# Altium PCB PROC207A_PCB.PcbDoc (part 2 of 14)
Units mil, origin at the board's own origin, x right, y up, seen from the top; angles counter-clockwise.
Board outline 4094.49 x 3724.79 mil, 8 copper layers (Top Layer, L2_GND1, L3_SIG1, L4_PWR1, L5_PWR2, L6_SIG2, L7_GND2, Bottom Layer), stack 58.1 mil thick; 584 components, 399 nets, 8440 pads, 5258 vias.
Unrouted connection lines stored in the file: 9.
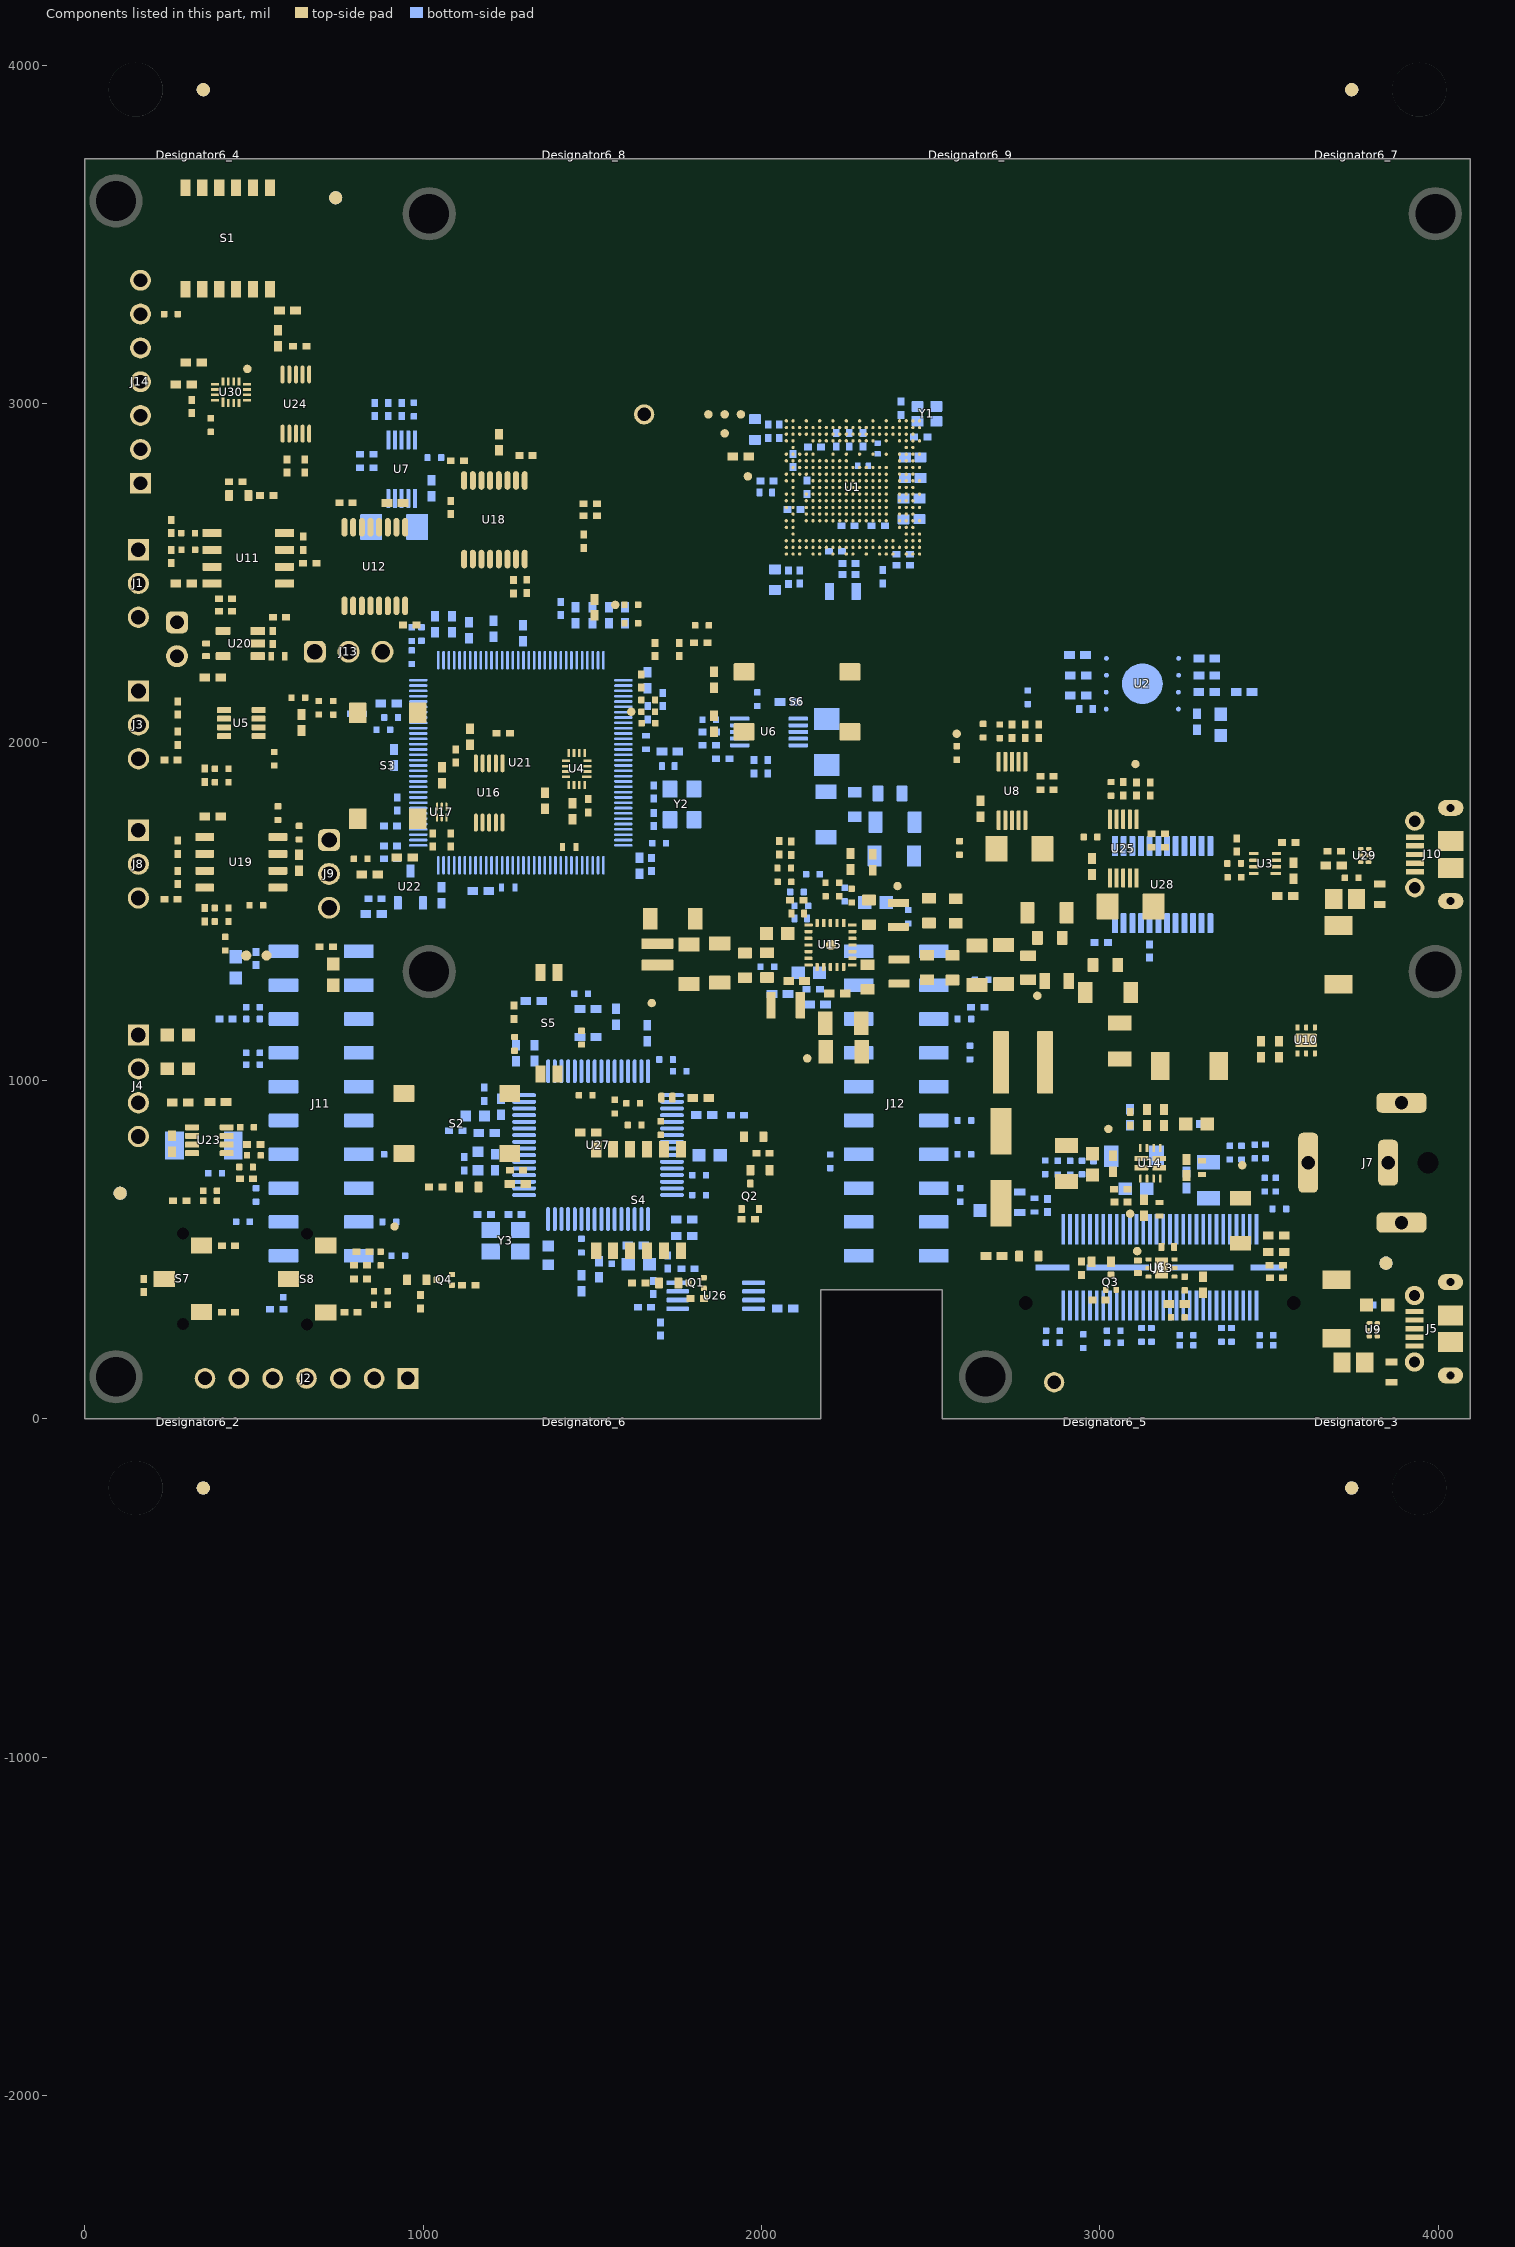
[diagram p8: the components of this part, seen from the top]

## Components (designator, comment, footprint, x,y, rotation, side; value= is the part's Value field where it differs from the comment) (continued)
R185 "CRCW04022K20JNED" 0402L 1679.65,388.39 r270 bottom value=2.2k
R186 "CRCW040233R2FKED" 0402 1273.96,1081.16 r90 bottom value=33.2
R187 "CRCW040233R2FKED" 0402 1326.93,1234.64 r180 bottom value=33.2
R188 "ERJ-2GE0R00X" FP-ERJ-2GE0R00X_0402-MFG 966.13,2251.35 r270 bottom value=0
R189 "ERJ-2GE0R00X" FP-ERJ-2GE0R00X_0402-MFG 1466.82,1256.68 r0 bottom value=0
R190 "ERJ-2GE0R00X" FP-ERJ-2GE0R00X_0402-MFG 905.18,2073.18 r0 bottom value=0
R191 "ERJ-2RKF1001X" 0402 1596.96,2375.29 r90 bottom value=1.00k
R192 "WSL1206R0400FEB" FP-WSL1206R0400FEB_1206-MFG 2193,2000.99 r90 bottom value=40m
R193 "WSL1206R0200FEB" FP-WSL1206R0200FEB_1206-MFG 2762.36,1684.93 r180 top value=20m
R194 "ERJ-2RKF1001X" 0402 1549.54,2375.29 r90 bottom value=1.00k
R195 "ERJ-2RKF1001X" 0402 1500.19,2375.63 r90 bottom value=1.00k
R196 "ERJ-2RKF1001X" 0402 1449.62,2375.63 r90 bottom value=1.00k
R197 "ERJ-2GE0R00X" FP-ERJ-2GE0R00X_0402-MFG 1467.94,1126.6 r270 top value=0
R198 "ERJ-2GE0R00X" FP-ERJ-2GE0R00X_0402-MFG 496.87,1047 r0 bottom value=0
R199 "ERJ-2GE0R00X" FP-ERJ-2GE0R00X_0402-MFG 1269.99,1108.46 r270 top value=0
R200 "WSL1206R0400FEB" FP-WSL1206R0400FEB_1206-MFG 914.18,2636.19 r0 bottom value=40m
R201 "ERJ-2GE0R00X" FP-ERJ-2GE0R00X_0402-MFG 2599.66,882 r0 bottom value=0
R202 "CRCW040249R9FKED" 0402L 1708.21,2126.64 r90 bottom value=49.9
R203 "CRCW040210K0FKED" 0402L 174.2,393.97 r90 top value=10.0k
R204 "CRCW04027K87FKED" 0402L 424.12,512.08 r0 top value=7.87k
R205 "CRCW040282K5FKED" 0402L 424.12,315.23 r180 top value=82.5k
R206 "CRCW040210K0FKED" 0402L 814.41,453.57 r180 top value=10.0k
R207 "CRCW04027K87FKED" 0402L 821.81,494.32 r0 top value=7.87k
R208 "CRCW040282K5FKED" 0402L 786.57,314.86 r180 top value=82.5k
R209 "CRCW040233R2FKED" 0402 1486.9,1211.99 r0 bottom value=33.2
R210 "ERJ-2GE0R00X" FP-ERJ-2GE0R00X_0402-MFG 384.82,726 r0 bottom value=0
R211 "ERJ-2GE0R00X" FP-ERJ-2GE0R00X_0402-MFG 904.66,782 r0 bottom value=0
R212 "ERJ-2GE0R00X" FP-ERJ-2GE0R00X_0402-MFG 2202.92,761.33 r90 bottom value=0
R213 "CRCW0402220RJNED" 0402 945.08,1658.85 r180 top value=220
R214 "ERJ-2GE0R00X" FP-ERJ-2GE0R00X_0402-MFG 815,1655.53 r0 top value=0
R215 "CRCW0402100KFKED" 0402 842.27,1609.44 r0 top value=100k
R216 "ERJ-2GE0R00X" FP-ERJ-2GE0R00X_0402-MFG 1717.94,1062.08 r0 bottom value=0
R217 "ERJ-2GE0R00X" FP-ERJ-2GE0R00X_0402-MFG 1758.3,1027.08 r180 bottom value=0
R218 "CRCW040210K0FKED" 0402L 1096.37,851.44 r0 bottom value=10.0k
R219 "ERJ-2GE0R00X" FP-ERJ-2GE0R00X_0402-MFG 3123.48,248.24 r270 bottom value=0
R220 "ERJ-2GE0R00X" FP-ERJ-2GE0R00X_0402-MFG 3152.67,248.24 r270 bottom value=0
R221 "ERJ-2GE0R00X" FP-ERJ-2GE0R00X_0402-MFG 2599.66,782 r0 bottom value=0
R222 "ERJ-2GE0R00X" FP-ERJ-2GE0R00X_0402-MFG 505.82,661.82 r90 bottom value=0
R223 "ERJ-2GE0R00X" FP-ERJ-2GE0R00X_0402-MFG 2587.42,661.82 r270 bottom value=0
R224 "ERJ-2GE0R00X" FP-ERJ-2GE0R00X_0402-MFG 467,582.78 r0 bottom value=0
R225 "ERJ-2GE0R00X" FP-ERJ-2GE0R00X_0402-MFG 3256.43,247.17 r180 bottom value=0
R226 "ERJ-2GE0R00X" FP-ERJ-2GE0R00X_0402-MFG 3256.43,217.48 r180 bottom value=0
R227 "ERJ-2GE0R00X" FP-ERJ-2GE0R00X_0402-MFG 3359.7,248.24 r270 bottom value=0
R228 "ERJ-2GE0R00X" FP-ERJ-2GE0R00X_0402-MFG 3389.38,248.24 r270 bottom value=0
R229 "ERJ-2GE0R00X" FP-ERJ-2GE0R00X_0402-MFG 3492.64,217.48 r0 bottom value=0
R230 "ERJ-2GE0R00X" FP-ERJ-2GE0R00X_0402-MFG 3492.64,247.17 r0 bottom value=0
R231 "CRCW040210K0FKED" 0402L 1663.56,2087.29 r90 bottom value=10.0k
R232 "ERJ-2GE0R00X" FP-ERJ-2GE0R00X_0402-MFG 899.66,582 r0 bottom value=0
R233 "ERJ-2RKF1001X" 0402 1054.11,1547.47 r270 bottom value=1.00k
R234 "CRCW04024K87FKED" 0402L 1406.98,2395.63 r270 bottom value=4.87k
R235 "ERJ-2GE0R00X" FP-ERJ-2GE0R00X_0402-MFG 369.87,674.49 r0 top value=0
R236 "CRCW0402330KFKED" 0402L 903.11,1752.47 r180 bottom value=330k
R237 "ERJ-2RKF1001X" 0402 1328.96,1081.22 r270 bottom value=1.00k
R238 "ERJ-2GE0R00X" FP-ERJ-2GE0R00X_0402-MFG 586.27,379.55 r90 bottom value=0
R239 "CRCW0402330KFKED" 0402L 903.11,1655.47 r0 bottom value=330k
R240 "ERJ-2GE0R00X" FP-ERJ-2GE0R00X_0402-MFG 926.22,482 r0 bottom value=0
R241 "ERJ-2GE0R00X" FP-ERJ-2GE0R00X_0402-MFG 3251.04,399.98 r90 top value=0
R242 "ERJ-2GE0R00X" FP-ERJ-2GE0R00X_0402-MFG 1467.83,511.73 r270 bottom value=0
R243 "ERJ-2GE0R00X" FP-ERJ-2GE0R00X_0402-MFG 1815.53,720.47 r0 bottom value=0
R244 "ERJ-2GE0R00X" FP-ERJ-2GE0R00X_0402-MFG 874.72,337.37 r0 top value=0
R245 "ERJ-2GE0R00X" FP-ERJ-2GE0R00X_0402-MFG 2067.24,1628.18 r0 top value=0
R246 "CRCW0402100KFKED" 0402L 2419.43,2523.33 r180 bottom value=100k
R247 "CRCW040210K0FKED" 0402L 1685.11,2274.26 r270 top value=10.0k
R248 "CRCW040233R2FKED" 0402 1519.16,441.79 r270 bottom locked value=33.2
R249 "CRCW040233R2FKED" 0402 1468.31,401.1 r270 bottom value=33.2
R250 "CRCW040210K0FKED" 0402L 1494.18,2669.49 r180 top value=10.0k
R251 "CRCW040233R2FKED" 0402 1830.79,897.64 r0 bottom value=33.2
R252 "ERJ-2GEJ511X" 0402L 1929.07,897.64 r0 bottom value=510
R253 "CRCW040210K0FKED" 0402L 635.36,3171.01 r180 top value=10.0k
R254 "ERJ-2GE0R00X" FP-ERJ-2GE0R00X_0402-MFG 414.56,1404.55 r90 top value=0
R255 "CRCW0402100KFKED" 0402L 1474.36,2594.42 r90 top value=100k
R256 "CRCW0402100KFKED" 0402L 1081.26,2694.18 r270 top value=100k
R257 "ERJ-2GE0R00X" FP-ERJ-2GE0R00X_0402-MFG 2576.93,1968.47 r90 top value=0
R258 "ERJ-2GEJ511X" 0402L 2946.06,444.73 r270 top value=510
R259 "ERJ-2GE0R00X" FP-ERJ-2GE0R00X_0402-MFG 3744.42,1599.14 r0 top value=0
R260 "CRCW040230K0FKED" 0402L 3692.79,1677.42 r0 top value=30.0k
R261 "CRCW040210K0FKED" 0402L 1757.13,2274.4 r90 top value=10.0k
R262 "CRCW0402220RJNED" 0402 1859.79,2054.47 r90 top value=220
R263 "ERJ-2GEJ511X" 0402L 2997.55,351.35 r180 top value=510
R264 "ERJ-2GE0R00X" FP-ERJ-2GE0R00X_0402-MFG 1615.08,2351.95 r0 top value=0
R265 "CRCW0402100KFKED" 0402 1859.79,2184.39 r270 top value=100k
R266 "ERJ-2GE0R00X" FP-ERJ-2GE0R00X_0402-MFG 734.45,2101.84 r270 top value=0
R267 "ERJ-2GE0R00X" FP-ERJ-2GE0R00X_0402-MFG 1665.13,2090.04 r180 top value=0
R268 "ERJ-2GE0R00X" FP-ERJ-2GE0R00X_0402-MFG 1665.13,2125.04 r180 top value=0
R269 "ERJ-2GE0R00X" FP-ERJ-2GE0R00X_0402-MFG 1615.08,2406.15 r0 top value=0
R270 "ERJ-2GE0R00X" FP-ERJ-2GE0R00X_0402-MFG 1665.95,2056.5 r180 top value=0
R271 "CRCW040210K0FKED" 0402L 315.66,2992.42 r90 top value=10.0k
R272 "RC0402FR-074K7L" 0402 321.95,3122.76 r0 top value=4.70k
R273 "ERJ-2GE0R00X" FP-ERJ-2GE0R00X_0402-MFG 404.36,1921.85 r180 top value=0
R274 "CRCW0402100KFKED" 0402L 597.17,2816.9 r270 top value=100k
R275 "CRCW0402100KFKED" 0402L 650.21,2816.9 r270 top value=100k
R276 "CRCW040210K0FKED" 0402L 1819.98,2294.33 r0 top value=10.0k
R277 "ERJ-2RKF1001X" 0402 598.62,3276 r0 top value=1.00k
R278 "ERJ-2GE0R00X" FP-ERJ-2GE0R00X_0402-MFG 2209.63,1544.82 r180 top value=0
R279 "ERJ-2GE0R00X" FP-ERJ-2GE0R00X_0402-MFG 2104.75,1557.54 r180 bottom value=0
R280 "ERJ-2GE0R00X" FP-ERJ-2GE0R00X_0402-MFG 2017.44,1336.5 r180 bottom value=0
R281 "ERJ-2GE0R00X" FP-ERJ-2GE0R00X_0402-MFG 2246.12,1549.78 r90 bottom value=0
R282 "ERJ-2GE0R00X" FP-ERJ-2GE0R00X_0402-MFG 2650.92,1297.66 r0 bottom value=0
R283 "CRCW040210K0FKED" 0402L 3558.84,1703.48 r180 top value=10.0k
R284 "ERJ-2GE0R00X" FP-ERJ-2GE0R00X_0402-MFG 2787,2133 r90 bottom value=0
R285 "ERJ-2GE0R00X" FP-ERJ-2GE0R00X_0402-MFG 371.87,2937.61 r90 top value=0
R286 "ERJ-2GE0R00X" FP-ERJ-2GE0R00X_0402-MFG 254.35,3265.75 r0 top value=0
R287 "ERJ-2GEJ511X" 0402L 1036.61,685.39 r180 top value=510
R288 "CRCW040210K0FKED" 0402L 2152.76,1269.69 r0 bottom value=10.0k
R289 "CRCW040219K1FKED" 0402 2054.68,1256.14 r0 bottom value=19.1k
R290 "ERJ-2GE0R00X" FP-ERJ-2GE0R00X_0402-MFG 882,2037 r0 bottom value=0
S1 "218-6LPST" SW_218-6LPST 421.89,3489.18 r270 top
S2 "PTS645SM43SMTR92 LFS" SW_PTS645SM43SMT 1099.52,872.95 r0 top
S3 "PTS645SM43SMTR92 LFS" SW_PTS645SM43SMT 895.12,1930.34 r270 top
S4 "218-6LPST" SW_218-6LPST 1636.51,646.87 r90 top
S5 "218-2LPST" SW_218-2LP 1371.54,1169.13 r270 top
S6 "PTS645SM43SMTR92 LFS" SW_PTS645SM43SMT 2104.9,2119.43 r180 top
S7 "CL-SB-12A-01T" SW_CL-SB-12A-01 289.32,413.65 r180 top
S8 "CL-SB-12A-01T" SW_CL-SB-12A-01 656.77,413.28 r180 top
TP1 "TESTPOINT" TP_25MIL-SMT 915.24,568.56 r270 top
TP2 "TESTPOINT" TP_25MIL-SMT 1843,2969.15 r90 top
TP3 "TESTPOINT" TP_25MIL-SMT 2576.93,2025.16 r90 top
TP4 "TESTPOINT" TP_25MIL-SMT 480.15,3103.58 r180 top
TP5 "TESTPOINT" TP_25MIL-SMT 1959.66,2785.99 r90 top
TP6 "TESTPOINT" TP_25MIL-SMT 1891.06,2913 r90 top
TP7 "TESTPOINT" TP_25MIL-SMT 3025.55,856.91 r90 top
TP8 "TESTPOINT" TP_25MIL-SMT 1614.95,2090.04 r90 top
TP9 "TESTPOINT" TP_25MIL-SMT 1567.54,2405.99 r90 top
TP11 "TESTPOINT" TP_25MIL-SMT 1939.12,2969.15 r90 top
TP12 "TESTPOINT" TP_25MIL-SMT 1891.06,2969.15 r90 top
TP13 "TESTPOINT" TP_25MIL-SMT 3089.63,606.28 r90 top
TP14 "TESTPOINT" TP_25MIL-SMT 3421.13,749.44 r90 top
TP15 "TESTPOINT" TP_25MIL-SMT 2135.09,1065.51 r90 top
TP16 "TESTPOINT" TP_25MIL-SMT 1675.43,1229.15 r270 top
TP17 "TESTPOINT" TP_25MIL-SMT 3105.44,1935.65 r90 top
TP18 "TESTPOINT" TP_25MIL-SMT 2402,1575 r90 top
TP19 "TESTPOINT" TP_25MIL-SMT 2815.34,1250.55 r90 top
TP20 "TESTPOINT" TP_25MIL-SMT 3110.45,495.88 r90 top
TP21 "TESTPOINT" TP_VIA_060RND040 2865,108 r90 top
TP22 "TESTPOINT" TP_VIA_060RND040 1653,2969.15 r90 top
U1 "XA6888DBSAPD" 0-MFG 2270.32,2753.25 r270 top
U2 "MX25V1635FZNQ03" FP-MX25V1635FZNQ03_WSON8-MFG 3126,2173 r0 bottom
U3 "TMP451AQDQFRQ1" DQF0008A 3488.89,1641.5 r180 top
U4 "TS3A5018RSVR" RSV0016A 1453.74,1921.26 r180 top
U5 "TCAN1044AVDDFRQ1" DDF0008A-MFG 462.45,2056.85 r180 top
U6 "INA228AIDGST" DGS0010A-MFG 2022.05,2030.52 r0 bottom
U7 "INA228AIDGST" DGS0010A-MFG 936.06,2807.15 r270 bottom
U8 "INA228AIDGST" DGS0010A-MFG 2740.47,1855.88 r270 top
U9 "TPD4E004DRYR" DRY0006A 3808.54,263.22 r0 top
U10 "TVS1800DRVR" DRV0006A 3610.07,1118.68 r270 top
U11 "CAT24C08WI-GT3" SOIC-8 482.9,2543.79 r180 top
U12 "TS3A44159PWR" PW0016A_N 856.89,2519.38 r90 top
U13 "TLV75533PDRVR" DRV0006A 3182.65,445.74 r0 top
U14 "TPS2121RUXR" RUX0012A 3149.19,755.07 r180 top
U15 "TPS65036501RAYRQ1" RAY0024B-MFG 2203.66,1400.77 r0 top locked
U16 "TS3A24157DGSR" DGS0010A_N 1194.96,1850.25 r90 top
U17 "SN74LVC1G11DSFR" DSF0006A 1054.8,1793.8 r90 top
U18 "TS3A44159PWR" PW0016A_N 1210.47,2657.7 r90 top
U19 "TCAN3403DRQ1" D0008B-MFG 462.28,1645.14 r180 top
U20 "TPS78417QDBVRQ1" DBV0005A-MFG 459.49,2291.81 r180 top
U21 "TM4C1294NCPDTT3" PDT0128A 1288.51,1939.32 r0 bottom locked
U22 "LM4040C25QDBZR" DBZ0003A_N 962.11,1572.47 r90 bottom
U23 "TLIN1039DDFRQ1" DDF0008A-MFG 367.95,823.53 r180 top
U24 "TS3A24157DGSR" DGS0010A_N 623.69,2999.86 r90 top
U25 "INA228AIDGST" DGS0010A-MFG 3069.32,1685.64 r270 top
U26 "93LC46B-I/ST" TSSOP-8 1864.18,363.88 r0 bottom
U27 "FT4232HL" LQFP64_N 1516.85,809.06 r0 bottom locked
U28 "TS3A27518EPWR" PW0024A-MFG 3185.8,1579.22 r270 bottom
U29 "TPD4E004DRYR" DRY0006A 3783.23,1665.25 r180 top
U30 "TS3A5018RSVR" RSV0016A 431.86,3034.84 r90 top
Y1 "FW4000044Q" FP-FW4000044Q_4-SMD-2.0x1.6mm-MFG 2489.06,2970.92 r180 bottom
Y2 "ECS-160-8-33Q-RES-TR" FP-ECS-160-8-33Q-RES-TR_SMT4_3MM2_2MM5-MFG 1764.81,1816.36 r270 bottom
Y3 "NX3225SA-12.000M-STD-CRS-2" NDK_NX3225SA 1243.27,526.6 r90 bottom
ZZ1 "This Assembly Note is for PCB labels only" AssemblyNoteLabel -334.65,4627.95 r0 top
ZZ2 "These assemblies are ESD sensitive, ESD precautions shall be observed." AssemblyNote -337.73,4557.31 r0 top
ZZ3 "These assemblies must be clean and free from flux and all contaminants. Use of no clean flux is not acceptable." AssemblyNote -336.61,4494.1 r0 top
ZZ4 "These assemblies must comply with workmanship standards IPC-A-610 Class 2, unless otherwise specified." AssemblyNote -336.61,4444.88 r0 top
ZZ5 "INDICATION FOR COMPONENTS D* ARE GIVEN AT THEIR CATHODE SIDE." AssemblyNote -336.61,4382.88 r0 top

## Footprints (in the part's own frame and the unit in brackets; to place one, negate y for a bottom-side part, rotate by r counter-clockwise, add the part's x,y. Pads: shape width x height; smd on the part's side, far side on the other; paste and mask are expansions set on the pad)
0-MFG [mm]
  round 0.25 smd paste+0 mask+0.05: A1(-5,5) A2(-4.5,5) A4(-3.5,5) A6(-2.5,5) A8(-1.5,5) A10(-0.5,5) A12(0.5,5) A14(1.5,5) A16(2.5,5) A18(3.5,5) A19(4,5) A20(4.5,5) A21(5,5) AA1(-5,-5) AA2(-4.5,-5) AA3(-4,-5) AA4(-3.5,-5) AA6(-2.5,-5) AA7(-2,-5) AA9(-1,-5) AA10(-0.5,-5) AA12(0.5,-5) AA13(1,-5) AA14(1.5,-5) AA16(2.5,-5) AA17(3,-5) AA19(4,-5) AA20(4.5,-5) AA21(5,-5) B1(-5,4.5) B2(-4.5,4.5) B3(-4,4.5) B4(-3.5,4.5) B5(-3,4.5) B6(-2.5,4.5) B7(-2,4.5) B8(-1.5,4.5) B9(-1,4.5) B10(-0.5,4.5) B11(0,4.5) B12(0.5,4.5) B13(1,4.5) B14(1.5,4.5) B15(2,4.5) B16(2.5,4.5) B17(3,4.5) B18(3.5,4.5) B19(4,4.5) B20(4.5,4.5) B21(5,4.5) C1(-5,4) C2(-4.5,4) C3(-4,4) C4(-3.5,4) C5(-3,4) C6(-2.5,4) C7(-2,4) C8(-1.5,4) C9(-1,4) C10(-0.5,4) C11(0,4) C12(0.5,4) C13(1,4) C14(1.5,4) C15(2,4) C16(2.5,4) C17(3,4) C18(3.5,4) C19(4,4) C20(4.5,4) C21(5,4) D1(-5,3.5) D2(-4.5,3.5) D3(-4,3.5) D4(-3.5,3.5) D6(-2.5,3.5) D7(-2,3.5) D8(-1.5,3.5) D9(-1,3.5) D10(-0.5,3.5) D11(0,3.5) D12(0.5,3.5) D13(1,3.5) D14(1.5,3.5) D15(2,3.5) D16(2.5,3.5) D17(3,3.5) D20(4.5,3.5) E2(-4.5,3) E3(-4,3) E19(4,3) E20(4.5,3) E21(5,3) F1(-5,2.5) F2(-4.5,2.5) F3(-4,2.5) F4(-3.5,2.5) F6(-2.5,2.5) F8(-1.5,2.5) F9(-1,2.5) F10(-0.5,2.5) F11(0,2.5) F12(0.5,2.5) F13(1,2.5) F14(1.5,2.5) F15(2,2.5) F16(2.5,2.5) F19(4,2.5) F20(4.5,2.5) F21(5,2.5) G2(-4.5,2) G3(-4,2) G8(-1.5,2) G9(-1,2) G10(-0.5,2) G11(0,2) G12(0.5,2) G13(1,2) G14(1.5,2) G15(2,2) G16(2.5,2) G20(4.5,2) G21(5,2) H1(-5,1.5) H2(-4.5,1.5) H3(-4,1.5) H4(-3.5,1.5) H6(-2.5,1.5) H8(-1.5,1.5) H9(-1,1.5) H10(-0.5,1.5) H11(0,1.5) H12(0.5,1.5) H13(1,1.5) H14(1.5,1.5) H15(2,1.5) H16(2.5,1.5) H19(4,1.5) H20(4.5,1.5) J2(-4.5,1) J3(-4,1) J4(-3.5,1) J8(-1.5,1) J9(-1,1) J10(-0.5,1) J11(0,1) J12(0.5,1) J13(1,1) J14(1.5,1) J15(2,1) J16(2.5,1) J19(4,1) J20(4.5,1) J21(5,1) K1(-5,0.5) K2(-4.5,0.5) K3(-4,0.5) K4(-3.5,0.5) K6(-2.5,0.5) K8(-1.5,0.5) K9(-1,0.5) K10(-0.5,0.5) K11(0,0.5) K12(0.5,0.5) K13(1,0.5) K14(1.5,0.5) K15(2,0.5) K16(2.5,0.5) K19(4,0.5) K20(4.5,0.5) L2(-4.5,0) L3(-4,0) L4(-3.5,0) L8(-1.5,0) L9(-1,0) L10(-0.5,0) L11(0,0) L12(0.5,0) L13(1,0) L14(1.5,0) L15(2,0) L16(2.5,0) L19(4,0) L20(4.5,0) L21(5,0) M1(-5,-0.5) M2(-4.5,-0.5) M3(-4,-0.5) M4(-3.5,-0.5) M6(-2.5,-0.5) M7(-2,-0.5) M8(-1.5,-0.5) M9(-1,-0.5) M10(-0.5,-0.5) M11(0,-0.5) M12(0.5,-0.5) M13(1,-0.5) M14(1.5,-0.5) M15(2,-0.5) M16(2.5,-0.5) M19(4,-0.5) M20(4.5,-0.5) M21(5,-0.5) N2(-4.5,-1) N3(-4,-1) N4(-3.5,-1) N7(-2,-1) N8(-1.5,-1) N9(-1,-1) N10(-0.5,-1) N11(0,-1) N12(0.5,-1) N13(1,-1) N14(1.5,-1) N15(2,-1) N16(2.5,-1) N19(4,-1) N20(4.5,-1) P1(-5,-1.5) P2(-4.5,-1.5) P3(-4,-1.5) P4(-3.5,-1.5) P6(-2.5,-1.5) P7(-2,-1.5) P8(-1.5,-1.5) P9(-1,-1.5) P10(-0.5,-1.5) P11(0,-1.5) P12(0.5,-1.5) P13(1,-1.5) P14(1.5,-1.5) P15(2,-1.5) P16(2.5,-1.5) P19(4,-1.5) P20(4.5,-1.5) P21(5,-1.5) R2(-4.5,-2) R3(-4,-2) R4(-3.5,-2) R7(-2,-2) R8(-1.5,-2) R9(-1,-2) R10(-0.5,-2) R11(0,-2) R12(0.5,-2) R13(1,-2) R14(1.5,-2) R15(2,-2) R16(2.5,-2) R19(4,-2) R20(4.5,-2) T1(-5,-2.5) T2(-4.5,-2.5) T3(-4,-2.5) T4(-3.5,-2.5) T7(-2,-2.5) T8(-1.5,-2.5) T9(-1,-2.5) T10(-0.5,-2.5) T11(0,-2.5) T12(0.5,-2.5) T13(1,-2.5) T14(1.5,-2.5) T15(2,-2.5) T16(2.5,-2.5) T19(4,-2.5) T20(4.5,-2.5) T21(5,-2.5) U2(-4.5,-3) U3(-4,-3) U4(-3.5,-3) U6(-2.5,-3) U7(-2,-3) U8(-1.5,-3) U9(-1,-3) U10(-0.5,-3) U11(0,-3) U12(0.5,-3) U13(1,-3) U14(1.5,-3) U15(2,-3) U16(2.5,-3) U19(4,-3) U20(4.5,-3) U21(5,-3) V1(-5,-3.5) V2(-4.5,-3.5) V3(-4,-3.5) V6(-2.5,-3.5) V7(-2,-3.5) V8(-1.5,-3.5) V9(-1,-3.5) V12(0.5,-3.5) V13(1,-3.5) V14(1.5,-3.5) V15(2,-3.5) V16(2.5,-3.5) V19(4,-3.5) V20(4.5,-3.5) W2(-4.5,-4) W3(-4,-4) W6(-2.5,-4) W7(-2,-4) W8(-1.5,-4) W9(-1,-4) W19(4,-4) W20(4.5,-4) W21(5,-4) Y1(-5,-4.5) Y2(-4.5,-4.5) Y3(-4,-4.5) Y4(-3.5,-4.5) Y5(-3,-4.5) Y6(-2.5,-4.5) Y7(-2,-4.5) Y8(-1.5,-4.5) Y9(-1,-4.5) Y10(-0.5,-4.5) Y11(0,-4.5) Y12(0.5,-4.5) Y13(1,-4.5) Y14(1.5,-4.5) Y15(2,-4.5) Y16(2.5,-4.5) Y17(3,-4.5) Y18(3.5,-4.5) Y19(4,-4.5) Y20(4.5,-4.5) Y21(5,-4.5)
  silkscreen extent -5.6,-5.6 5.6,5.6, body extent -6.1,-6.1 6.1,6.1, height 0.25
0402 [mm] "0402 from SM-752 data"
  rect 0.8x0.6 smd: 1(-0.6,0) 2(0.6,0)
  silkscreen extent -1.22,-0.52 1.22,0.52, body extent -0.55,-0.3 0.55,0.3, height 0.6
0402_070 [mil] "SMD, 2-Leads, Body 1.2x0.7mm, Height 0.7mm"
  rect 15x24 smd: 1(-20,0) 2(20,0)
  body extent -24,-14 24,14, height 28
0402L [mm] "0402 from SM-752 data"
  rect 0.6x0.5 smd: 1(-0.5,0) 2(0.5,0)
  body extent -0.55,-0.3 0.55,0.3, height 0.6
0603 [mm] "0603 from SM-752 data"
  rect 1x0.95 smd: 1(-0.8,0) 2(0.8,0)
  silkscreen extent -1.52,-0.69 1.52,0.69, body extent -0.87,-0.47 0.87,0.47, height 1
0603L [mm] "0603 from SM-752 data"
  rect 0.8x0.85 smd: 1(-0.7,0) 2(0.7,0)
  silkscreen extent -0.07,-0.33 0.07,0.33, body extent -0.87,-0.47 0.87,0.47, height 1
0603S [mil]
  rect 20x35 smd: 1(-30,0) 2(30,0)
  body extent -34,-19 34,19, height 39
0805 [mm] "0805 from SM-752 data"
  rect 1.3x1.5 smd: 1(-0.85,0) 2(0.85,0)
  silkscreen extent -1.72,-0.97 1.72,0.97, body extent -1.1,-0.72 1.1,0.72, height 1.45
1206_180 [mm] "1206_180"
  rect 1.1x1.6 smd: 1(-1.7,0) 2(1.7,0)
  silkscreen extent -0.9,-1 0.9,1, body extent -1.75,-0.95 1.75,0.95, height 1.8
1206_180L [mm] "1206_180"
  rect 1.1x1.75 smd: 1(-1.35,0) 2(1.35,0)
  silkscreen extent -0.4,-0.77 0.4,0.77, body extent -1.75,-0.95 1.75,0.95, height 1.8
AssemblyNote [mil] "Assembly Note"
AssemblyNoteLabel [mil] "Assembly Note for PCB Labels"
BRAKE_WAY_HOLES1X3_CUST [mm]
  round 0.373 hole 0.5 unplated mask+0.152: ""(-0.838,0.746) ""(0,0.746) ""(0.838,0.746)
CE_Mark_5mm [mil] "Minimum text height for CE Mark"
  silkscreen extent -138,-98 138,98
CONN_105017-0001 [mm] "Molex Micro USB-B"
  rect 0.4x1.35 smd: 1(-1.3,1.35) 2(-0.65,1.35) 3(0,1.35) 4(0.65,1.35) 5(1.3,1.35)
  oval 1.2x1.9 hole 0.6 slot 1.3 at 90 deg: 6(-3.5,-1.35) 9(3.5,-1.35)
  rect 1.5x1.9 smd: 7(-1,-1.35) 8(1,-1.35)
  round 1.45 hole 0.85: 10(2.5,1.35) 11(-2.5,1.35)
  Top Layer region: -3.499,-2.301 -2.299,-2.301 -2.299,-0.401 -3.499,-0.401
  Top Layer region: 3.501,-0.401 2.301,-0.401 2.301,-2.301 3.501,-2.301
  silkscreen extent -4.1,-0.2 4.1,1.4, body extent -4.1,-3.93 4.1,1.5, height 2.72
CUI_PJ-063AH [mm] "DC POWER JACK, R/A, TH"
  rrect50% 1.5x4.5 hole 1 square: 1(-4.5,0)
  rrect50% 1.5x3.45 hole 1 square: 2(1.5,0)
  oval 1.35x1.3 hole 1.6 unplated mask+0.102: ALIGN(4.5,0)
  rrect50% 3.75x1.5 hole 1 square: S1(2.5,-4.5) S2(2.5,4.5)
  body extent -5.5,-5.15 7.5,5.15, height 9
D0008B-MFG [mm]
  rrect17% 1.4x0.6 smd paste+0 mask+0: 1(-2.75,1.905) 2(-2.75,0.635) 3(-2.75,-0.635) 4(-2.75,-1.905) 5(2.75,-1.905) 6(2.75,-0.635) 7(2.75,0.635) 8(2.75,1.905)
  silkscreen extent -4.14,-2.5 1.5,2.5, body extent -3,-2.45 3,2.45, height 1.75
DBV0005A-MFG [mm]
  rrect17% 1.1x0.6 smd paste+0 mask+0: 1(-1.3,0.95) 2(-1.3,0) 3(-1.3,-0.95) 4(1.3,-0.95) 5(1.3,0.95)
  silkscreen extent -1.4,-1.53 0.87,1.86, body extent -1.95,-1.78 1.95,1.78, height 0.25
DBZ0003A_N [mm] "SOT23, 3-Leads, Body 2.9x1.3mm, Pitch 0.95mm, Lead Span 2.4mm, IPC Medium Density"
  rrect17% 1x0.6 smd: 1(-1.2,0.95) 2(-1.2,-0.95) 3(1.2,0)
  silkscreen extent 0.2,-1.5 0.7,1.5, body extent -1.26,-1.46 1.26,1.46, height 0.98
DDF0008A-MFG [mm]
  rrect22% 1.05x0.45 smd paste+0 mask+0: 1(-1.3,0.975) 2(-1.3,0.325) 3(-1.3,-0.325) 4(-1.3,-0.975) 5(1.3,-0.975) 6(1.3,-0.325) 7(1.3,0.325) 8(1.3,0.975)
  silkscreen extent -2.5,-1.48 0.4,1.48, body extent -1.92,-1.73 1.92,1.73, height 0.25
DGS0010A-MFG [mm]
  rrect33% 1.45x0.3 smd paste+0 mask+0: 1(-2.2,1) 2(-2.2,0.5) 3(-2.2,0) 4(-2.2,-0.5) 5(-2.2,-1) 6(2.2,-1) 7(2.2,-0.5) 8(2.2,0) 9(2.2,0.5) 10(2.2,1)
  silkscreen extent -3.41,-1.55 1.05,1.55, body extent -2.45,-1.5 2.45,1.5, height 1.1
DGS0010A_N [mm] "TSSOP, 10-Leads, Body 3x3mm, Pitch 0.5mm, IPC Medium Density"
  oval 1.35x0.3 smd: 1(-2.225,1) 2(-2.225,0.5) 3(-2.225,0) 4(-2.225,-0.5) 5(-2.225,-1) 6(2.225,-1) 7(2.225,-0.5) 8(2.225,0) 9(2.225,0.5) 10(2.225,1)
  silkscreen extent -2.75,-1.55 0.9,1.55, body extent -2.45,-1.5 2.45,1.5, height 0.96
DQF0008A [mm] "SON-8"
  rrect40% 0.8x0.25 smd: 1(-0.8,0.75)
  rrect40% 0.7x0.25 smd: 2(-0.85,0.25) 3(-0.85,-0.25) 4(-0.85,-0.75) 5(0.85,-0.75) 6(0.85,-0.25) 7(0.85,0.25) 8(0.85,0.75)
  silkscreen extent -1.15,-1.17 0.38,1.17, body extent -1.05,-1.05 1.05,1.05, height 0.81
DRV0006A [mm] "SON, 6-Leads, Body 2x2mm, Pitch 0.65mm, Thermal Pad 1.6x1mm, TI Recommended"
  rrect33% 0.45x0.3 smd: 1(-0.975,0.65) 2(-0.975,0) 3(-0.975,-0.65) 4(0.975,-0.65) 5(0.975,0) 6(0.975,0.65)
  rrect14% 1x0.7 on Top Paste: 7(0,0.45) 7(0,-0.45)
  rrect10% 1x1.6 smd paste-0.5: 7(0,0)
  silkscreen extent -1.05,-1.2 1.05,1.2, body extent -1.05,-1.05 1.05,1.05, height 0.81
DRY0006A [mm] "USON-6"
  rrect67% 0.45x0.3 smd paste-0.05 mask-0.05: 1(-0.275,0.5)
  rrect67% 0.4x0.3 smd paste-0.05 mask-0.05: 2(-0.3,0) 3(-0.3,-0.5) 4(0.3,-0.5) 5(0.3,0) 6(0.3,0.5)
  body extent -0.5,-0.72 0.5,0.73, height 0.58
DSF0006A [mm] "TI recommended land pattern"
  rrect59% 0.6x0.17 smd mask+0.045: 1(-0.4,0.35) 2(-0.4,0) 3(-0.4,-0.35) 4(0.4,-0.35) 5(0.4,0) 6(0.4,0.35)
  silkscreen extent -0.6,-0.63 0.6,0.63, body extent -0.5,-0.5 0.5,0.5, height 0.48
FCC_disclaimer [mil]
Fiducial10-20 [mm]
  round 1 smd mask+0.5: 1(0,0)
  Top Layer keep-out circle w1.178: c0,0 r0.5
FIDUCIAL10-20 [mm]
  round 1 smd mask+0.5: 1(0,0)
  Top Layer keep-out circle w1.178: c0,0 r0.5
FP-0022288072_HDR7-MFG [mm]
  rrect6% 1.57x1.57 hole 1.02 paste-2539.97 mask+0: 1(-7.62,-2.925)
  round 1.57 hole 1.02 paste-2539.97 mask+0: 2(-5.08,-2.925) 3(-2.54,-2.925) 4(0,-2.925) 5(2.54,-2.925) 6(5.08,-2.925) 7(7.62,-2.925)
  silkscreen extent -9.11,-3.05 9.01,1.27, body extent -9.11,-3.81 9.12,7.95, height 0.25
FP-CGA4J3X7S1A106K125AE_0805-MFG [mm]
  rrect13% 0.8x1.05 smd paste+0 mask+0: 1(-0.925,0) 2(0.925,0)
  silkscreen extent -0.15,-0.75 0.15,0.75, body extent -1.2,-0.62 1.2,0.63, height 1.5
FP-ECS-160-8-33Q-RES-TR_SMT4_3MM2_2MM5-MFG [mm]
  rrect9% 1.3x1.1 smd paste+0 mask+0: 1(-1.15,-0.9) 2(1.15,-0.9) 3(1.15,0.9) 4(-1.15,0.9)
  silkscreen extent -1.52,-1.96 0.13,1.3, body extent -1.6,-1.25 1.6,1.25, height 0.8
FP-ERJ-2GE0R00X_0402-MFG [mm]
  rrect21% 0.475x0.5 smd paste+0 mask+0: 1(-0.513,0) 2(0.513,0)
  silkscreen extent -0.53,-0.63 0.53,0.63, body extent -0.5,-0.25 0.5,0.25, height 0.4
FP-FW4000044Q_4-SMD-2.0x1.6mm-MFG [mm]
  rrect13% 0.9x0.8 smd paste+0 mask+0: 1(-0.7,-0.55) 2(0.7,-0.55) 3(0.7,0.55) 4(-0.7,0.55)
  silkscreen extent -1.05,-1.1 1.01,1.13, body extent -1,-0.8 1,0.8, height 0.55
FP-GCJ21BR71C475KA01L_0805-MFG [mm]
  rrect14% 0.7x1.3 smd paste+0 mask+0: 1(-1,0) 2(1,0)
  silkscreen extent -0.28,-0.72 0.28,0.72, body extent -1,-0.63 1,0.63, height 1.45
FP-GCM188D70E226ME36D_0603-MFG [mm]
  rrect13% 0.75x0.9 smd paste+0 mask+0: 1(-0.775,0) 2(0.775,0)
  silkscreen extent -0.03,-0.5 0.03,0.5, body extent -0.8,-0.4 0.8,0.4, height 1
FP-GCM188D70J106ME36D_0603-MFG [mm]
  rrect13% 0.75x0.9 smd paste+0 mask+0: 1(-0.775,0) 2(0.775,0)
  body extent -0.8,-0.4 0.8,0.4, height 1
FP-GRM31CR70J226ME19K_1206-MFG [mm]
  rrect10% 1.05x1.6 smd paste+0 mask+0: 1(-1.475,0) 2(1.475,0)
  silkscreen extent -0.58,-0.9 0.58,0.9, body extent -2.1,-1 2.1,1, height 0.25
FP-GRT155C71A225KE13D_0402-MFG [mm]
  rrect22% 0.45x0.6 smd paste+0 mask+0: 1(-0.475,0) 2(0.475,0)
  silkscreen extent -0.5,0.7 0.5,0.7, body extent -0.5,-0.25 0.5,0.25, height 0.7
FP-GRT155R70J105KE01D_0402-MFG [mm]
  rrect25% 0.4x0.5 smd paste+0 mask+0: 1(-0.4,0) 2(0.4,0)
  silkscreen extent -0.53,-0.63 0.53,0.63, body extent -0.5,-0.25 0.5,0.25, height 0.55
"FP-LQM2MPZR10MJHL_0806 (2016)-MFG" [mm]
  rrect13% 0.8x2.4 smd paste-1000 mask-1000: 1(-0.8,0) 2(0.8,0)
  silkscreen extent -1.1,-1.5 1.1,1.5, body extent -1.3,-1.3 1.3,1.3, height 0.25
FP-MPZ2012S300ATD25_0805-MFG [mm]
  rrect13% 0.8x1.2 smd paste+0 mask+0: 1(-0.9,0) 2(0.9,0)
  silkscreen extent -0.12,-0.72 0.13,0.72, body extent -1,-0.63 1,0.63, height 1.05
FP-MX25V1635FZNQ03_WSON8-MFG [mm]
  round 0.36 smd paste+0 mask+0: 1(-2.72,1.905) 2(-2.72,0.635) 3(-2.7,-0.635) 4(-2.7,-1.905) 5(2.72,-1.905) 6(2.72,-0.635) 7(2.7,0.635) 8(2.7,1.905)
  round 3.06 smd paste+0 mask+0: 9(0,0)
  Top Layer region: 1.7,2 1.7,-2 -1.7,-2 -1.7,1.6 -1.3,2 1.7,2
  Top Layer region: -3,2.105 -2.6,2.105 -2.523,2.09 -2.459,2.046 -2.415,1.982 -2.4,1.905 -2.4,1.905 -2.427,1.805 -2.5,1.732 -2.6,1.705 -2.6,1.705 -3,1.705
  Top Layer region: 3,1.705 2.6,1.705 2.523,1.72 2.459,1.764 2.415,1.828 2.4,1.905 2.4,1.905 2.415,1.982 2.459,2.046 2.523,2.09 2.6,2.105 2.6,2.105 3,2.105
  Top Layer region: 3,0.435 2.6,0.435 2.523,0.45 2.459,0.494 2.415,0.558 2.4,0.635 2.4,0.635 2.415,0.712 2.459,0.776 2.523,0.82 2.6,0.835 2.6,0.835 3,0.835
  Top Layer region: 3,-0.835 2.6,-0.835 2.523,-0.82 2.459,-0.776 2.415,-0.712 2.4,-0.635 2.4,-0.635 2.415,-0.558 2.459,-0.494 2.523,-0.45 2.6,-0.435 2.6,-0.435 3,-0.435
  Top Layer region: -3,-0.435 -2.6,-0.435 -2.523,-0.45 -2.459,-0.494 -2.415,-0.558 -2.4,-0.635 -2.4,-0.635 -2.427,-0.735 -2.5,-0.808 -2.6,-0.835 -2.6,-0.835 -3,-0.835
  Top Layer region: -3,0.835 -2.6,0.835 -2.523,0.82 -2.459,0.776 -2.415,0.712 -2.4,0.635 -2.4,0.635 -2.427,0.535 -2.5,0.462 -2.6,0.435 -2.6,0.435 -3,0.435
  Top Layer region: 3,-2.105 2.6,-2.105 2.523,-2.09 2.459,-2.046 2.415,-1.982 2.4,-1.905 2.4,-1.905 2.415,-1.828 2.459,-1.764 2.523,-1.72 2.6,-1.705 2.6,-1.705 3,-1.705
  Top Layer region: -3,-1.705 -2.6,-1.705 -2.523,-1.72 -2.459,-1.764 -2.415,-1.828 -2.4,-1.905 -2.4,-1.905 -2.427,-2.005 -2.5,-2.078 -2.6,-2.105 -2.6,-2.105 -3,-2.105
  silkscreen extent -3.05,-2.55 3.05,3.12, body extent -3,-2.49 3,2.49, height 0.8
FP-RC0402FR-1047K5L_0402-MFG [mm]
  rrect20% 0.5x0.6 smd paste+0 mask+0: 1(-0.5,0) 2(0.5,0)
  silkscreen extent -0.5,-0.52 0.5,0.67, body extent -0.5,-0.25 0.5,0.25, height 0.4
FP-SSM3K35AMFV,L3F_SOT-723-MFG [mm]
  rrect25% 0.45x0.4 smd paste+0 mask+0: 1(-0.575,0.4) 2(-0.575,-0.4)
  rrect22% 0.45x0.5 smd paste+0 mask+0: 3(0.575,0)
  silkscreen extent -0.43,-0.98 0.71,0.72, body extent -0.9,-0.73 0.9,0.73, height 0.25
FP-TFM252012ALVA1R5MTAA_1008-MFG [mm]
  rrect14% 0.7x2 smd paste+0 mask+0: 1(-1.1,0) 2(1.1,0)
  silkscreen extent -0.38,-1.1 0.38,1.1, body extent -1.55,-1.2 1.55,1.2, height 0.25
FP-TLMY1100-GS15_0603-MFG [mm]
  rrect17% 0.6x0.8 smd paste+0 mask+0: 1(-0.725,0) 2(0.725,0)
  silkscreen extent -1.61,-0.45 0.05,0.45, body extent -1.12,-0.55 1.12,0.55, height 0.25
FP-WSL1206R0100FEB_1206-MFG [mm]
  rrect6% 1.65x1.93 smd paste+0 mask+0: 1(-1.725,0) 2(1.725,0)
  silkscreen extent -0.53,-0.93 0.53,0.93, body extent -2.65,-1.06 2.65,1.06, height 0.25
FP-WSL1206R0200FEB_1206-MFG [mm]
  rrect6% 1.65x1.93 smd paste+0 mask+0: 1(-1.725,0) 2(1.725,0)
  silkscreen extent -0.53,-0.93 0.53,0.93, body extent -2.65,-1.06 2.65,1.06, height 0.25
FP-WSL1206R0400FEB_1206-MFG [mm]
  rrect6% 1.65x1.93 smd paste+0 mask+0: 1(-1.725,0) 2(1.725,0)
  silkscreen extent -0.53,-0.93 0.53,0.93, body extent -1.6,-0.8 1.6,0.8, height 0.89
FP-XGL5050-472MEC_SMT2_5MM28_5MM48-MFG [mm]
  rrect8% 1.18x4.7 smd paste+0 mask+0: 1(-1.655,0) 2(1.655,0)
  silkscreen extent -3.4,-2.84 2.74,2.84, body extent -2.84,-2.94 2.84,2.94, height 0.25
IEC_HotSurface_Small [mil]
  silkscreen extent -107,-93 107,92
Label_650x200 [mil] "Thermal Transfer Label"
  round 1 on Mech14: 0(0,0)
  silkscreen extent -325,-100 325,100
LQFP64_N [mm] "Thin QFP, 64-Leads, Body 10x10mm, Pitch 0.5mm, IPC Medium Density"
  oval 1.8x0.3 smd: 1(-5.55,3.75) 2(-5.55,3.25) 3(-5.55,2.75) 4(-5.55,2.25) 5(-5.55,1.75) 6(-5.55,1.25) 7(-5.55,0.75) 8(-5.55,0.25) 9(-5.55,-0.25) 10(-5.55,-0.75) 11(-5.55,-1.25) 12(-5.55,-1.75) 13(-5.55,-2.25) 14(-5.55,-2.75) 15(-5.55,-3.25) 16(-5.55,-3.75) 33(5.55,-3.75) 34(5.55,-3.25) 35(5.55,-2.75) 36(5.55,-2.25) 37(5.55,-1.75) 38(5.55,-1.25) 39(5.55,-0.75) 40(5.55,-0.25) 41(5.55,0.25) 42(5.55,0.75) 43(5.55,1.25) 44(5.55,1.75) 45(5.55,2.25) 46(5.55,2.75) 47(5.55,3.25) 48(5.55,3.75)
  oval 0.3x1.8 smd: 17(-3.75,-5.55) 18(-3.25,-5.55) 19(-2.75,-5.55) 20(-2.25,-5.55) 21(-1.75,-5.55) 22(-1.25,-5.55) 23(-0.75,-5.55) 24(-0.25,-5.55) 25(0.25,-5.55) 26(0.75,-5.55) 27(1.25,-5.55) 28(1.75,-5.55) 29(2.25,-5.55) 30(2.75,-5.55) 31(3.25,-5.55) 32(3.75,-5.55) 49(3.75,5.55) 50(3.25,5.55) 51(2.75,5.55) 52(2.25,5.55) 53(1.75,5.55) 54(1.25,5.55) 55(0.75,5.55) 56(0.25,5.55) 57(-0.25,5.55) 58(-0.75,5.55) 59(-1.25,5.55) 60(-1.75,5.55) 61(-2.25,5.55) 62(-2.75,5.55) 63(-3.25,5.55) 64(-3.75,5.55)
  silkscreen extent -6.96,-4.25 4.25,4.25, body extent -5,-5 5,5, height 1.6
NDK_NX3225SA [mm] "NDK"
  rect 1.2x1.4 smd: 1(-0.8,1.1) 2(-0.8,-1.1) 3(0.8,-1.1) 4(0.8,1.1)
  body extent -1.3,-1.65 1.3,1.65, height 0.7
PDT0128A [mm] "Thin QFP, 128-Leads, Body 14x14mm, Pitch 0.4mm"
  oval 1.4x0.2 smd: 1(-7.7,6.2) 2(-7.7,5.8) 3(-7.7,5.4) 4(-7.7,5) 5(-7.7,4.6) 6(-7.7,4.2) 7(-7.7,3.8) 8(-7.7,3.4) 9(-7.7,3) 10(-7.7,2.6) 11(-7.7,2.2) 12(-7.7,1.8) 13(-7.7,1.4) 14(-7.7,1) 15(-7.7,0.6) 16(-7.7,0.2) 17(-7.7,-0.2) 18(-7.7,-0.6) 19(-7.7,-1) 20(-7.7,-1.4) 21(-7.7,-1.8) 22(-7.7,-2.2) 23(-7.7,-2.6) 24(-7.7,-3) 25(-7.7,-3.4) 26(-7.7,-3.8) 27(-7.7,-4.2) 28(-7.7,-4.6) 29(-7.7,-5) 30(-7.7,-5.4) 31(-7.7,-5.8) 32(-7.7,-6.2) 65(7.7,-6.2) 66(7.7,-5.8) 67(7.7,-5.4) 68(7.7,-5) 69(7.7,-4.6) 70(7.7,-4.2) 71(7.7,-3.8) 72(7.7,-3.4) 73(7.7,-3) 74(7.7,-2.6) 75(7.7,-2.2) 76(7.7,-1.8) 77(7.7,-1.4) 78(7.7,-1) 79(7.7,-0.6) 80(7.7,-0.2) 81(7.7,0.2) 82(7.7,0.6) 83(7.7,1) 84(7.7,1.4) 85(7.7,1.8) 86(7.7,2.2) 87(7.7,2.6) 88(7.7,3) 89(7.7,3.4) 90(7.7,3.8) 91(7.7,4.2) 92(7.7,4.6) 93(7.7,5) 94(7.7,5.4) 95(7.7,5.8) 96(7.7,6.2)
  oval 0.2x1.4 smd: 33(-6.2,-7.7) 34(-5.8,-7.7) 35(-5.4,-7.7) 36(-5,-7.7) 37(-4.6,-7.7) 38(-4.2,-7.7) 39(-3.8,-7.7) 40(-3.4,-7.7) 41(-3,-7.7) 42(-2.6,-7.7) 43(-2.2,-7.7) 44(-1.8,-7.7) 45(-1.4,-7.7) 46(-1,-7.7) 47(-0.6,-7.7) 48(-0.2,-7.7) 49(0.2,-7.7) 50(0.6,-7.7) 51(1,-7.7) 52(1.4,-7.7) 53(1.8,-7.7) 54(2.2,-7.7) 55(2.6,-7.7) 56(3,-7.7) 57(3.4,-7.7) 58(3.8,-7.7) 59(4.2,-7.7) 60(4.6,-7.7) 61(5,-7.7) 62(5.4,-7.7) 63(5.8,-7.7) 64(6.2,-7.7) 97(6.2,7.7) 98(5.8,7.7) 99(5.4,7.7) 100(5,7.7) 101(4.6,7.7) 102(4.2,7.7) 103(3.8,7.7) 104(3.4,7.7) 105(3,7.7) 106(2.6,7.7) 107(2.2,7.7) 108(1.8,7.7) 109(1.4,7.7) 110(1,7.7) 111(0.6,7.7) 112(0.2,7.7) 113(-0.2,7.7) 114(-0.6,7.7) 115(-1,7.7) 116(-1.4,7.7) 117(-1.8,7.7) 118(-2.2,7.7) 119(-2.6,7.7) 120(-3,7.7) 121(-3.4,7.7) 122(-3.8,7.7) 123(-4.2,7.7) 124(-4.6,7.7) 125(-5,7.7) 126(-5.4,7.7) 127(-5.8,7.7) 128(-6.2,7.7)
  silkscreen extent -8.3,-6.3 6.3,6.88, body extent -8,-8 8,8, height 1.07
PW0016A_N [mm] "TSOP, 16-Leads, Body 5x4.4mm, Pitch 0.65mm, IPC Medium Density"
  oval 1.4x0.45 smd: 1(-2.95,2.275) 2(-2.95,1.625) 3(-2.95,0.975) 4(-2.95,0.325) 5(-2.95,-0.325) 6(-2.95,-0.975) 7(-2.95,-1.625) 8(-2.95,-2.275) 9(2.95,-2.275) 10(2.95,-1.625) 11(2.95,-0.975) 12(2.95,-0.325) 13(2.95,0.325) 14(2.95,0.975) 15(2.95,1.625) 16(2.95,2.275)
  silkscreen extent -3.5,-2.55 1.85,2.75, body extent -3.21,-2.5 3.21,2.5, height 1
PW0024A-MFG [mm]
  rrect22% 1.5x0.45 smd paste+0 mask+0: 1(-2.9,3.575) 2(-2.9,2.925) 3(-2.9,2.275) 4(-2.9,1.625) 5(-2.9,0.975) 6(-2.9,0.325) 7(-2.9,-0.325) 8(-2.9,-0.975) 9(-2.9,-1.625) 10(-2.9,-2.275) 11(-2.9,-2.925) 12(-2.9,-3.575) 13(2.9,-3.575) 14(2.9,-2.925) 15(2.9,-2.275) 16(2.9,-1.625) 17(2.9,-0.975) 18(2.9,-0.325) 19(2.9,0.325) 20(2.9,0.975) 21(2.9,1.625) 22(2.9,2.275) 23(2.9,2.925) 24(2.9,3.575)
  silkscreen extent -4.37,-3.95 1.78,3.95, body extent -3.2,-3.9 3.2,3.9, height 1.2
RAY0024B-MFG [mm]
  rrect40% 0.625x0.25 smd paste+0 mask+0: 1(-1.637,1.5) 7(-1.637,-1.5) 13(1.637,-1.5) 19(1.637,1.5)
  rrect40% 0.6x0.25 smd paste+0 mask+0: 2(-1.65,1) 3(-1.65,0.5) 4(-1.65,0) 5(-1.65,-0.5) 6(-1.65,-1) 14(1.65,-1) 15(1.65,-0.5) 16(1.65,0) 17(1.65,0.5) 18(1.65,1)
  rrect40% 0.25x0.6 smd paste+0 mask+0: 8(-1,-1.65) 9(-0.5,-1.65) 10(0,-1.65) 11(0.5,-1.65) 12(1,-1.65) 20(1,1.65) 21(0.5,1.65) 22(0,1.65) 23(-0.5,1.65) 24(-1,1.65)
  round 0.777 smd paste-25.4 mask+0: ""(0.037,-0.003)
  Top Layer region: -1.95,0.075 -1.943,0.1 -1.925,0.118 -1.9,0.125 -1.9,0.125 -1.4,0.125 -1.378,0.12 -1.361,0.106 -1.361,0.106 -1.344,0.092 -1.322,0.088 -1.322,0.088 -0.426,0.088 -0.406,0.091 -0.39,0.102 -0.379,0.118 -0.375,0.138 -0.376,0.138 -0.376,0.601 -0.369,0.626 -0.35,0.644 -0.325,0.651 -0.326,0.651 0.456,0.651 0.48,0.644 0.499,0.626 0.505,0.601 0.505,0.601 0.505,0.1 0.509,0.081 0.52,0.065 0.536,0.054 0.556,0.05 0.556,0.05 1.303,0.05 1.324,0.055 1.342,0.068 1.352,0.088 1.352,0.088 1.362,0.107 1.379,0.12 1.4,0.125 1.4,0.125 1.9,0.125 1.925,0.118 1.943,0.1 1.95,0.075 1.95,0.075 1.95,-0.075 1.943,-0.1 1.925,-0.118 1.9,-0.125 1.9,-0.125 0.556,-0.125 0.536,-0.129 0.52,-0.14 0.509,-0.156 0.506,-0.175 0.505,-0.175 0.505,-0.601 0.499,-0.626 0.48,-0.644 0.456,-0.651 0.456,-0.651 -0.326,-0.651 -0.35,-0.644 -0.369,-0.626 -0.375,-0.601 -0.375,-0.601 -0.376,-0.138 -0.379,-0.118 -0.39,-0.102 -0.406,-0.091 -0.425,-0.088 -0.426,-0.087 -1.322,-0.088 -1.344,-0.092 -1.361,-0.106 -1.361,-0.106 -1.378,-0.12 -1.4,-0.125 -1.4,-0.125 -1.9,-0.125 -1.925,-0.118 -1.943,-0.1 -1.95,-0.075 -1.95,-0.075
  silkscreen extent -2.56,1.55 -2.31,1.8, body extent -2.05,-2.05 2.05,2.05, height 0.25
RSV0016A [mm] "QFN, 16-Leads, Body 1.8x2.6mm, Pitch 0.4mm, TI Recommended"
  rect 0.7x0.2 smd: 1(-0.75,0.6)
  rect 0.6x0.2 smd: 2(-0.8,0.2) 3(-0.8,-0.2) 4(-0.8,-0.6) 9(0.8,-0.6) 10(0.8,-0.2) 11(0.8,0.2) 12(0.8,0.6)
  rect 0.2x0.6 smd: 5(-0.6,-1.2) 6(-0.2,-1.2) 7(0.2,-1.2) 8(0.6,-1.2) 13(0.6,1.2) 14(0.2,1.2) 15(-0.2,1.2) 16(-0.6,1.2)
  silkscreen extent -1.08,-1.33 1.08,1.45, body extent -0.92,-1.32 0.92,1.33, height 0.56
RUX0012A [mm] "VQFN-HR-12"
  rrect25% 1.05x0.4 smd: 1(-0.675,0.325) 2(-0.675,-0.375) 7(0.675,-0.375) 8(0.675,0.325)
  rrect40% 0.2x0.6 smd: 3(-0.75,-1.15) 4(-0.25,-1.15) 5(0.25,-1.15) 6(0.75,-1.15) 9(0.75,1.15) 10(0.25,1.15) 11(-0.25,1.15) 12(-0.75,1.15)
  silkscreen extent -1.15,-1.4 1.15,1.35, body extent -1.05,-1.3 1.05,1.3, height 1
Samtec_QSH-030-01-X-D-A [mm] "Receptacle, 0.5 mm, 30x2, TH"
  rect 2.27x0.279 smd: 1(-2.865,7.25) 2(2.865,7.25) 3(-2.865,6.75) 4(2.865,6.75) 5(-2.865,6.25) 6(2.865,6.25) 7(-2.865,5.75) 8(2.865,5.75) 9(-2.865,5.25) 10(2.865,5.25) 11(-2.865,4.75) 12(2.865,4.75) 13(-2.865,4.25) 14(2.865,4.25) 15(-2.865,3.75) 16(2.865,3.75) 17(-2.865,3.25) 18(2.865,3.25) 19(-2.865,2.75) 20(2.865,2.75) 21(-2.865,2.25) 22(2.865,2.25) 23(-2.865,1.75) 24(2.865,1.75) 25(-2.865,1.25) 26(2.865,1.25) 27(-2.865,0.75) 28(2.865,0.75) 29(-2.865,0.25) 30(2.865,0.25) 31(-2.865,-0.25) 32(2.865,-0.25) 33(-2.865,-0.75) 34(2.865,-0.75) 35(-2.865,-1.25) 36(2.865,-1.25) 37(-2.865,-1.75) 38(2.865,-1.75) 39(-2.865,-2.25) 40(2.865,-2.25) 41(-2.865,-2.75) 42(2.865,-2.75) 43(-2.865,-3.25) 44(2.865,-3.25) 45(-2.865,-3.75) 46(2.865,-3.75) 47(-2.865,-4.25) 48(2.865,-4.25) 49(-2.865,-4.75) 50(2.865,-4.75) 51(-2.865,-5.25) 52(2.865,-5.25) 53(-2.865,-5.75) 54(2.865,-5.75) 55(-2.865,-6.25) 56(2.865,-6.25) 57(-2.865,-6.75) 58(2.865,-6.75) 59(-2.865,-7.25) 60(2.865,-7.25)
  round 0 hole 1.02 unplated: MH1(2.67,10.065) MH2(2.67,-10.065)
  rect 0.43x2.54 smd: MP1(0,8.065) MP4(0,-8.065)
  rect 0.43x4.7 smd: MP2(0,3.175) MP3(0,-3.175)
  silkscreen extent -3.85,-10.66 3.62,10.66, body extent -3.75,-10.64 3.75,10.67, height 3.25
Samtec_SSM-110-x-DV [mm] "Receptacle, 2.54mm, 10x2, SMT"
  rrect10% 1.02x2.22 smd: 1(-11.43,2.825) 2(-11.43,-2.825) 3(-8.89,2.825) 4(-8.89,-2.825) 5(-6.35,2.825) 6(-6.35,-2.825) 7(-3.81,2.825) 8(-3.81,-2.825) 9(-1.27,2.825) 10(-1.27,-2.825) 11(1.27,2.825) 12(1.27,-2.825) 13(3.81,2.825) 14(3.81,-2.825) 15(6.35,2.825) 16(6.35,-2.825) 17(8.89,2.825) 18(8.89,-2.825) 19(11.43,2.825) 20(11.43,-2.825)
  silkscreen extent -13.02,-2.54 12.7,2.54, body extent -12.7,-3.52 12.7,3.52, height 7.42
SM_RADIAL_6.3BMM [mm] "Nichicon 6.3x7.7"
  rect 3.5x1.6 smd: 1(-2.7,0) 2(2.7,0)
  silkscreen extent -3.4,-3.4 3.4,3.4, body extent -3.4,-3.4 3.4,3.4, height 8
SOD-128 [mm] "SMD, 2-Leads, Body 4x2.7mm, Height 1.1mm"
  rect 1.4x2.1 smd paste-0.1: 1(-2.2,0) 2(2.2,0)
  silkscreen extent -3.45,-1.45 2.95,1.45, body extent -2.5,-1.35 2.5,1.35, height 1.11
SOD-882 [mm] "Skyworks"
  rrect42% 0.475x0.75 smd mask+0.05: 1(-0.412,0) 2(0.412,0)
  silkscreen extent -1.1,-0.35 -0.87,0.35, body extent -0.5,-0.3 0.5,0.3, height 0.5
SOIC-8 [mm] "duplicate of SO-8.  SOIC, 8-Leads, Body 5.0x4.0mm (max), Pitch 1.27mm, IPC Medium Density"
  rrect17% 1.45x0.6 smd: 1(-2.725,1.905) 2(-2.725,0.635) 3(-2.725,-0.635) 4(-2.725,-1.905) 5(2.725,-1.905) 6(2.725,-0.635) 7(2.725,0.635) 8(2.725,1.905)
  silkscreen extent -3.5,-2.5 0.9,2.5, body extent -3,-2.45 3,2.45, height 1.63
SolderJumper [mil] "Solder Jumper"
  round 30 smd paste-40: 1(-30,0) 2(30,0)
  Top Layer region: 2.5,-50 24.19,-45.05 41.59,-31.17 51.25,-11.13 51.25,11.13 41.59,31.17 24.19,45.05 2.5,50 2.5,50
  Top Layer region: -2.5,-50 -24.19,-45.05 -41.59,-31.17 -51.25,-11.13 -51.25,11.13 -41.59,31.17 -24.19,45.05 -2.5,50 -2.5,50
SOT-323 [mm] "Diodes Inc recommended land pattern.  2016-02-24"
  rrect21% 0.6x0.47 smd: 1(-0.95,0.65) 2(-0.95,-0.65) 3(0.95,0)
  silkscreen extent -1.14,-1.22 0.77,1.22, body extent -1.13,-1.13 1.12,1.12, height 1.13
Sullins_xxC07SAAN [mm] "Header, 2.54 mm, 7x1, TH"
  rect 1.55x1.55 hole 1.016: 1(-7.62,0)
  round 1.55 hole 1.016: 2(-5.08,0) 3(-2.54,0) 4(0,0) 5(2.54,0) 6(5.08,0) 7(7.62,0)
  silkscreen extent -8.89,-1.27 8.89,1.7, body extent -8.89,-1.27 8.89,1.27, height 8.38
SW_218-2LP [mm] "SMD, 4-Leads, Body 3.71x5.8mm, Pitch 1.27mm"
  rect 1.27x0.76 smd: 1(-3.81,0.635) 2(-3.81,-0.635) 3(3.81,-0.635) 4(3.81,0.635)
  silkscreen extent -2.9,-1.86 2.9,2.09, body extent -4.22,-1.86 4.22,1.85, height 2.62
SW_218-6LPST [mm] "SMD, 12-Leads, Body 5.8x8.79mm"
  rect 1.27x0.76 smd: 1(-3.81,3.175) 2(-3.81,1.905) 3(-3.81,0.635) 4(-3.81,-0.635) 5(-3.81,-1.905) 6(-3.81,-3.175) 7(3.81,-3.175) 7(3.81,-3.175) 8(3.81,-1.905) 9(3.81,-0.635) 10(3.81,0.635) 11(3.81,1.905) 12(3.81,3.175)
  silkscreen extent -2.9,-4.4 2.9,4.7, body extent -4.22,-4.4 4.22,4.39, height 2.62
SW_CL-SB-12A-01 [mm] "SMD, 3-Leads, Body 8.5x3.5mm, Pitch 2.5mm"
  rect 1.6x1.2 smd: 1(-1.4,2.5) 2(1.4,0) 3(-1.4,-2.5)
  round 0 hole 0.9 unplated: MH1(0,3.4) MH2(0,-3.4)
  silkscreen extent -2.71,-4.25 1.75,4.25, body extent -1.75,-4.25 1.75,4.25, height 5.5
SW_PTS645SM43SMT [mm] "SMD, 4-Leads, Body 6x6mm"
  rrect8% 1.55x1.3 smd: 1(-3.975,2.25) 2(3.975,2.25) 3(-3.975,-2.25) 4(3.975,-2.25)
  body extent -4.5,-3 4.5,3, height 4.3
TFM201610ALMA [mm] "TDK"
  rrect17% 0.6x1.6 smd: 1(-0.9,0) 2(0.9,0)
  body extent -1.1,-0.9 1.1,0.9, height 1
TI_Stacked_Overlay_Small [mil]
  silkscreen extent -418,-98 418,98
TP_25MIL-SMT [mil]
  round 25 smd mask-2.5: 1(0,0)
TP_VIA_060RND040 [mil] "TP_VIA_060RND040"
  round 60 hole 40: 1(0,0)
TSSOP-8 [mm] "TSSOP, 8-Leads, Body 3.1x4.5mm (max), Pitch 0.65mm, IPC Medium Density"
  rrect50% 1.7x0.35 smd: 1(-2.85,0.975) 2(-2.85,0.325) 3(-2.85,-0.325) 4(-2.85,-0.975) 5(2.85,-0.975) 6(2.85,-0.325) 7(2.85,0.325) 8(2.85,0.975)
  silkscreen extent -2.4,-1.55 1.6,1.75, body extent -3.2,-1.55 3.2,1.55, height 1.07
TSW-102-07-G-S [mm] "Samtec 100mil, 1x2, 230 mil above insulator"
  rrect50% 1.65x1.65 hole 1.016: 1(-1.27,0)
  round 1.65 hole 1.016: 2(1.27,0)
  silkscreen extent -3.17,-1.27 2.54,1.27, body extent -2.54,-1.27 2.54,1.27, height 8.38
WEEE_Minimum [mil] "WEEElie bin"
  silkscreen extent -95,-172 99,104
Wurth_61300311021 [mm] "Header, 2.54 mm, 3x1, R/A, TH"
  rect 1.6x1.6 hole 1.1: 1(-2.54,0)
  round 1.6 hole 1.1: 2(0,0) 3(2.54,0)
  silkscreen extent -4.25,-4.04 3.81,-1.5, body extent -3.81,-10.04 3.81,0.32, height 2.55
WURTH_61300311121 [mm] "Header, 2.54mm, 3x1, TH"
  rrect50% 1.65x1.65 hole 1.15: 1(-2.54,0)
  round 1.65 hole 1.15: 2(0,0) 3(2.54,0)
  body extent -3.81,-1.27 3.81,1.27, height 8.54
Wurth_61300411021 [mm] "Header, 2.54 mm, 4x1, R/A, TH"
  rect 1.6x1.6 hole 1.1: 1(-3.81,0)
  round 1.6 hole 1.1: 2(-1.27,0) 3(1.27,0) 4(3.81,0)
  silkscreen extent -5.5,-4.04 5.08,-1.5, body extent -5.08,-10.04 5.08,0.32, height 2.55

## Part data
C1 C2 C4 C5 C7 C8 C10 C11 C12 C14 C16 C21 C25 C26 C45 C85 C121 C134: library part CMP-0078265-1, "CAP, CERM, 0.22 µF, 16 V,+/- 10%, X7R, AEC-Q200 Grade 1, 0402", Cap_Case=0402, Manufacturer=MuRata, Supplier Part Number 1=490-10671-1-ND, TempCo=X7R, Tolerance_%=10%, Value2=16V, ValueDisplayed=0.22µF
C3 C20 C27 C75 C76 C77 C78 C83 C117 C155 C156: library part CMP-0089543-1, "10µF ±10% 10V Ceramic Capacitor X7S 0805 (2012 Metric)", Digikey Part Number=445-173805-1-ND, Manufacturer=TDK, Mouser Part Number=810-CG4J3X7S1A106KAE, Operating Temperature Range="-55°C to +125°C", TempCo=22%, Temperature Characteristic=X7S, Tolerance_%=10%, ValueDisplayed=10uF
C6: library part CMP-0006330-2, "CAP, CERM, 0.047 uF, 50 V, +/- 10%, X7R, AEC-Q200 Grade 1, 0402", Cap_Case=0402, Manufacturer=TDK, Supplier Part Number 1=445-6897-1-ND, TempCo=X7R, Tolerance_%=10%, Value1="0.06407 ohm", Value2=50V, ValueDisplayed=0.047uF
C9 C24 C44: library part CMP-0048366-1, "22 µF ±20% 2.5V Ceramic Capacitor X7T 0603 (1608 Metric)", Digikey Part Number=490-GCM188D70E226ME36DCT-ND, Manufacturer=Murata, Mouser Part Number=81-GCM188D70E226M36D, Operating Temperature Range="-55°C to +125°C", TempCo=+22/-33%, Temperature Characteristic=X7T, Tolerance_%=20%, ValueDisplayed=22uF
C13 C15 C19: library part CMP-0086534-1, "Chip Multilayer Ceramic Capacitors for Automotive", Manufacturer=Murata, TempCo=-33+22%, Tolerance_%=20%
C17 C42 C79 C87 C105 C112 C124: library part CMP-0094968-1, "Multi-Layer Ceramic Capacitor 2.2uF 10V X7S ±10% 0402 Paper T/R", Manufacturer=Murata, Operating Temperature Range="-55°C to +125°C", TempCo=22%, Temperature Characteristic=X7S, Tolerance_%=10%, ValueDisplayed=2.2uF
C18 C22: library part CMP-0088425-1, "1µF ±10% 6.3V Ceramic Capacitor X7R 0402 (1005 Metric)", Digikey Part Number=490-18216-1-ND, Manufacturer=Murata, Mouser Part Number=81-GRT155R70J105KE1D, Operating Temperature Range="-55°C to +125°C", TempCo=15%, Temperature Characteristic=X7R, Tolerance_%=10%, ValueDisplayed=1uF
C30: library part CMP-0012608-3, "CAP, Polymer Hybrid, 68 uF, 35 V, +/- 20%, 35 ohm, 6.3x7.7 SMD", Manufacturer=Panasonic, Supplier Part Number 1=P15474CT-ND, Tolerance_%=20%, Value1="35 ohm", Value2=35V, ValueDisplayed=68uF
C31 C34 C36 C37 C38 C40 C41 C48 C52 C53 C56 C57 C58 C59 C60 C61 C63 C65 C67 C69 C94 C95 C99 C104 C106 C107 C109 C110 C113 C116 C123 C125 C126 C133 C135 C136 C138 C140 C142 C143 C144 C146 C150 C152 C153 C154 C158: library part CMP-0006356-2, "CAP, CERM, 0.1 uF, 50 V, +/- 10%, X7R, AEC-Q200 Grade 1, 0402", Cap_Case=0402, Manufacturer=MuRata, Supplier Part Number 1=490-10672-1-ND, TempCo=X7R, Tolerance_%=10%, Value1=Unknown, Value2=50V, ValueDisplayed=0.1uF
C32 C33: library part CMP-0006367-2, "CAP, CERM, 4.7 pF, 50 V, +/- 2%, C0G/NP0, 0402", Cap_Case=0402, Manufacturer=MuRata, Supplier Part Number 1=490-8102-1-ND, TempCo=C0G/NP0, Tolerance_%=2%, Value1=Unknown, Value2=50V, ValueDisplayed=4.7pF
C35 C54 C62 C73 C88 C100 C149 C151: library part CMP-0086540-3, "CAP, 1uF, 25V, ±10%, X7R, 0603", Manufacturer=Samsung, TempCo=15%, Tolerance_%=10%
C39 C111: library part CMP-0006361-2, "CAP, CERM, 4700 pF, 50 V, +/- 10%, X7R, AEC-Q200 Grade 1, 0402", Cap_Case=0402, Manufacturer=MuRata, Supplier Part Number 1=490-4915-1-ND, TempCo=X7R, Tolerance_%=10%, Value1=Unknown, Value2=50V, ValueDisplayed=4700pF
C43 C49 C50 C74 C137: library part CMP-0008702-2, "CAP, CERM, 4.7 uF, 50 V, +/- 10%, X7R, 1206", Cap_Case=1206_180, Manufacturer=TDK, Supplier Part Number 1=445-8032-1-ND, TempCo=X7R, Tolerance_%=10%, Value1="0.003158 ohm", Value2=50V, ValueDisplayed=4.7uF
C46 C47: library part CMP-0006564-3, "CAP, CERM, 10 uF, 10 V, +/- 20%, X5R, 0402", Cap_Case=0402, Manufacturer=MuRata, TempCo=X5R, Tolerance_%=20%, Value1=Unknown, Value2=10V, ValueDisplayed=10uF
C51 C66 C68 C93 C108 C114 C127: library part CMP-0006349-2, "CAP, CERM, 1 uF, 10 V, +/- 10%, X7S, AEC-Q200 Grade 1, 0402", Cap_Case=0402, Manufacturer=MuRata, Supplier Part Number 1=81-GCM155C71A105KE8D, TempCo=X7S, Tolerance_%=10%, Value1=Unknown, Value2=10V, ValueDisplayed=1uF
C55: library part CMP-0008944-2, "CAP, CERM, 47 uF, 10 V, +/- 10%, X5R, 1206", Cap_Case=1206, Manufacturer=MuRata, Supplier Part Number 1=81-GRM31CR61A476KE5L, TempCo=X5R, Tolerance_%=10%, Value1=Unknown, Value2=10V, ValueDisplayed=47uF
C64: library part CMP-0081062-1, "CAP, CERM, 10 µF, 25 V,+/- 5%, X7R, AEC-Q200 Grade 1, 1206", Cap_Case=1206_180, Manufacturer=Kemet, Supplier Part Number 1=399-15734-1-ND, TempCo=X7R, Tolerance_%=5%, Value2=25V, ValueDisplayed=10µF
C70 C71 C80 C81 C89 C90 C91: library part CMP-0092150-1, "Chip Multilayer Ceramic Capacitors for General Purpose, 1206, 22uF, X7R, 15%, 20%, 6.3V", Manufacturer=Murata, Operating Temperature Range="-55°C to +125°C", TempCo=15%, Temperature Characteristic=X7R, Tolerance_%=20%, ValueDisplayed=22uF
C72 C82 C103: library part CMP-0008940-2, "CAP, CERM, 47 uF, 6.3 V, +/- 20%, X5R, 1206", Cap_Case=1206, Manufacturer=MuRata, Supplier Part Number 1=490-3907-1-ND, TempCo=X5R, Tolerance_%=20%, Value1="0.003 ohm", Value2=6.3V, ValueDisplayed=47uF
C84 C92 C119 C120: library part CMP-0064967-2, "CAP, CERM, 0.47 uF, 10 V,+/- 10%, X7S, 0402", Cap_Case=0402, Manufacturer=MuRata, Supplier Part Number 1=490-14427-1-ND, TempCo=X7S, Tolerance_%=10%, Value1=Unknown, Value2=10V, ValueDisplayed=0.47uF
C86 C96 C157: library part CMP-0007497-5, "CAP, CERM, 10 uF, 10 V, +/- 10%, X5R, 0603", Cap_Case=0603, Manufacturer=MuRata, Supplier Part Number 1=81-GRM188Z71A106MA3D, TempCo=X7R, Tolerance_%=20%, Value1=Unknown, Value2=10V, ValueDisplayed=10uF
C97 C98: library part CMP-0860185-1, "CAP, CERM, 8 pF, 50 V,+/- 6.25%, C0G/NP0, 0402", Cap_Case=0402, Manufacturer=Yageo, TempCo=C0G/NP0, Tolerance_%=6.25%, Value2=50V, ValueDisplayed=8pF
C102 C115 C118 C128 C130: library part CMP-0006352-2, "CAP, CERM, 0.01 uF, 25 V, +/- 10%, X7R, 0402", Cap_Case=0402, Manufacturer=MuRata, Supplier Part Number 1=490-6043-2-ND, TempCo=X7R, Tolerance_%=10%, Value1=Unknown, Value2=25V, ValueDisplayed=0.01uF
C131: library part CMP-0094778-1, "Multilayer Ceramic Capacitors MLCC - SMD/SMT 0805 4.7uF 10%, 16VDC,  X7R 15%", Manufacturer=Murata, Operating Temperature Range="-55°C to +125°C", TempCo=15%, Temperature Characteristic=X7R, Tolerance_%=10%, ValueDisplayed=4.7uF
C132: library part CMP-0006218-2, "CAP, CERM, 220 pF, 50 V, +/- 5%, C0G/NP0, 0402", Cap_Case=0402, Manufacturer="Wurth Elektronik", Supplier Part Number 1=732-7477-1-ND, TempCo=C0G/NP0, Tolerance_%=5%, Value1=Unknown, Value2=50V, ValueDisplayed=220pF
C139 C141 C145: library part CMP-0007058-4, "CAP, CERM, 4.7 uF, 10 V, +/- 10%, X7S, 0603", Cap_Case=0603, Manufacturer=TDK, Supplier Part Number 1=445-14258-1-ND, TempCo=X7S, Tolerance_%=10%, Value1=Unknown, Value2=10V, ValueDisplayed=4.7uF
C147 C148: library part CMP-0087060-3, "Cap Ceramic 8pF 50V C0G 0.5pF SMD 0402 125C Paper T/R", Manufacturer="Murata Electronics North America", TempCo=30ppm/°C
"CAUTION HOT SURFACE1": library part CMP-0074837-2, "IEC 61010-1 Hot Surface Warning", Manufacturer="Texas Instruments"
D1 D8 D12: library part CMP-0078758-2, "Diode, Schottky, 30 V, 2 A, AEC-Q101, SOD-128", Manufacturer=Nexperia, Value1=2A, Value2=0.36V
D2: library part CMP-0077017-3, "Diode, Schottky, 30 V, 5 A, SOD-128", Manufacturer=Nexperia, Value1=5A, Value2=0.36V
